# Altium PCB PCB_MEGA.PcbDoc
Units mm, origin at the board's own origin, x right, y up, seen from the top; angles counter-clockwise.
Board outline 45.21 x 64 mm, 2 copper layers (M1(Top_copper), M2(Bottom copper), stack 0.325 mm thick; 31 components, 22 nets, 132 pads, 19 vias.
Unrouted connection lines stored in the file: 13.
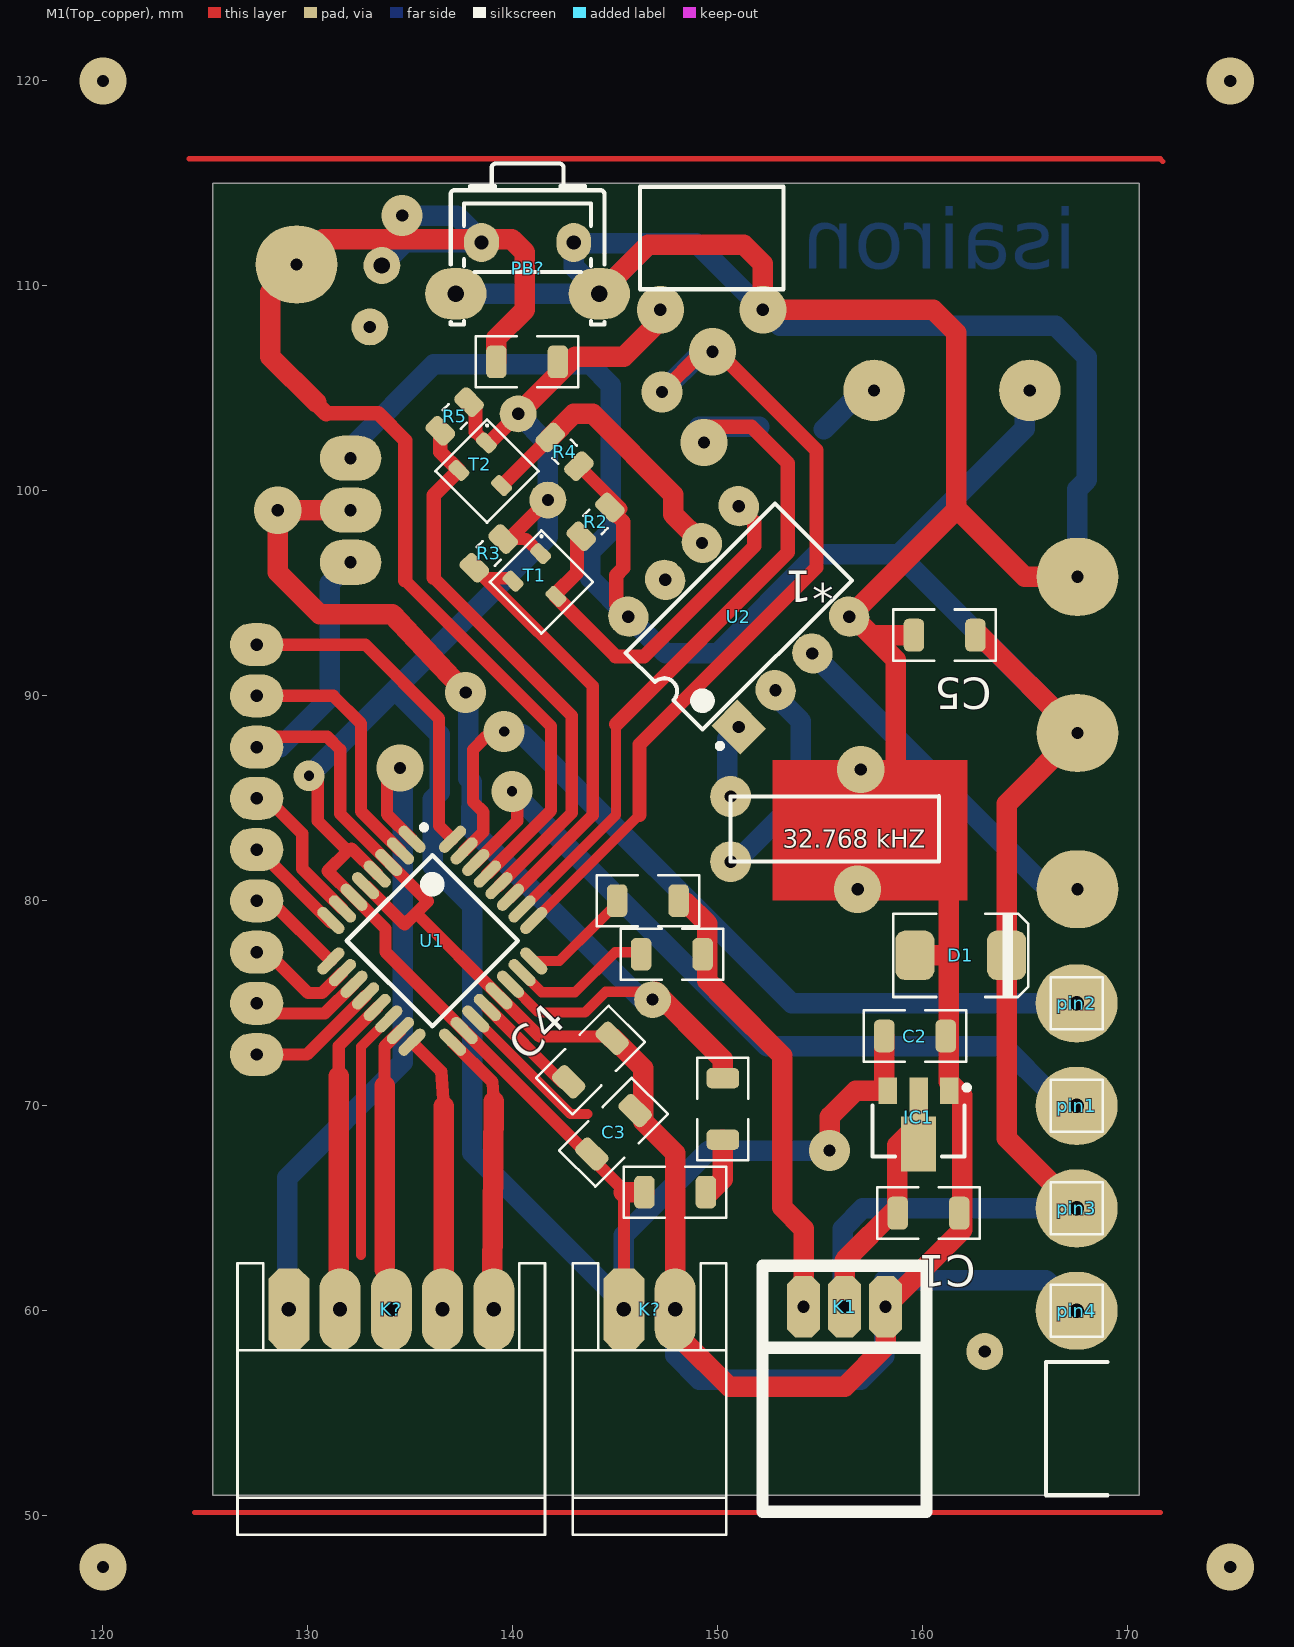
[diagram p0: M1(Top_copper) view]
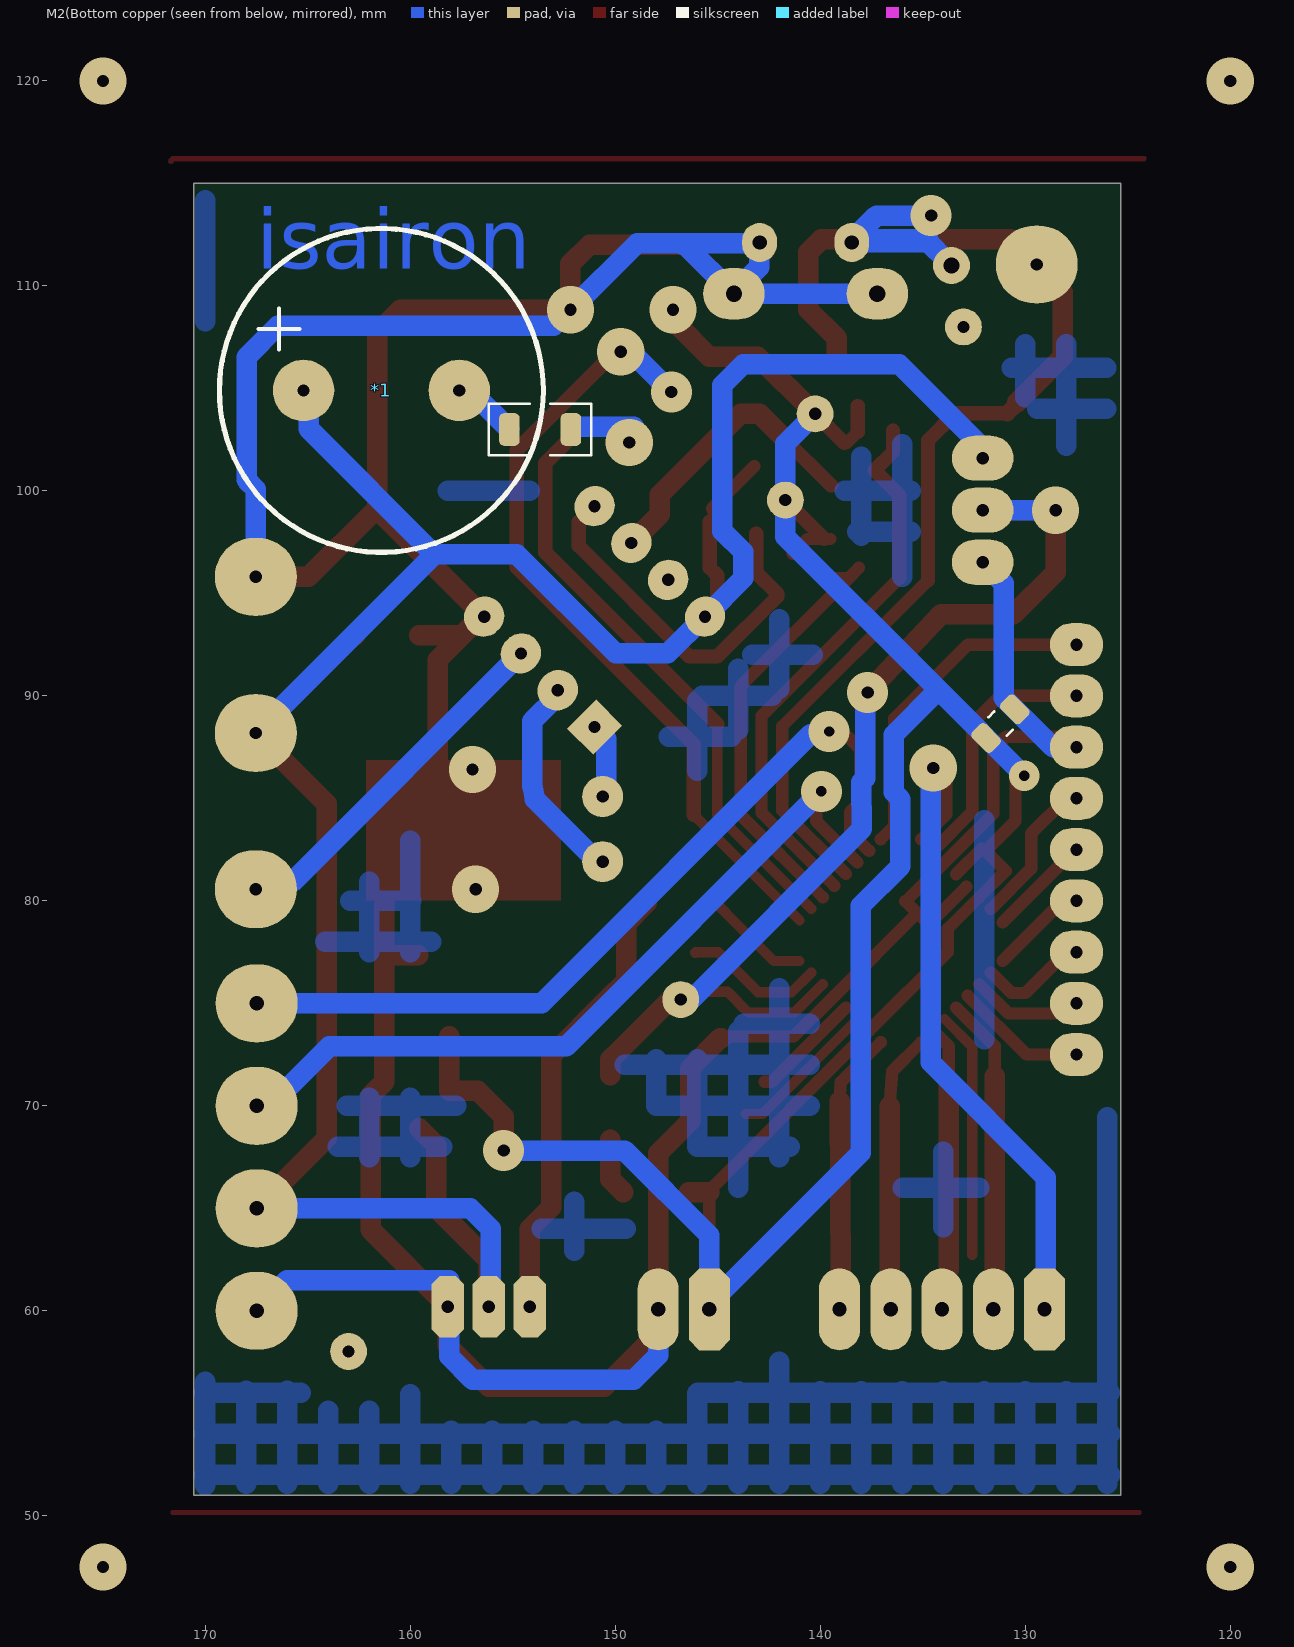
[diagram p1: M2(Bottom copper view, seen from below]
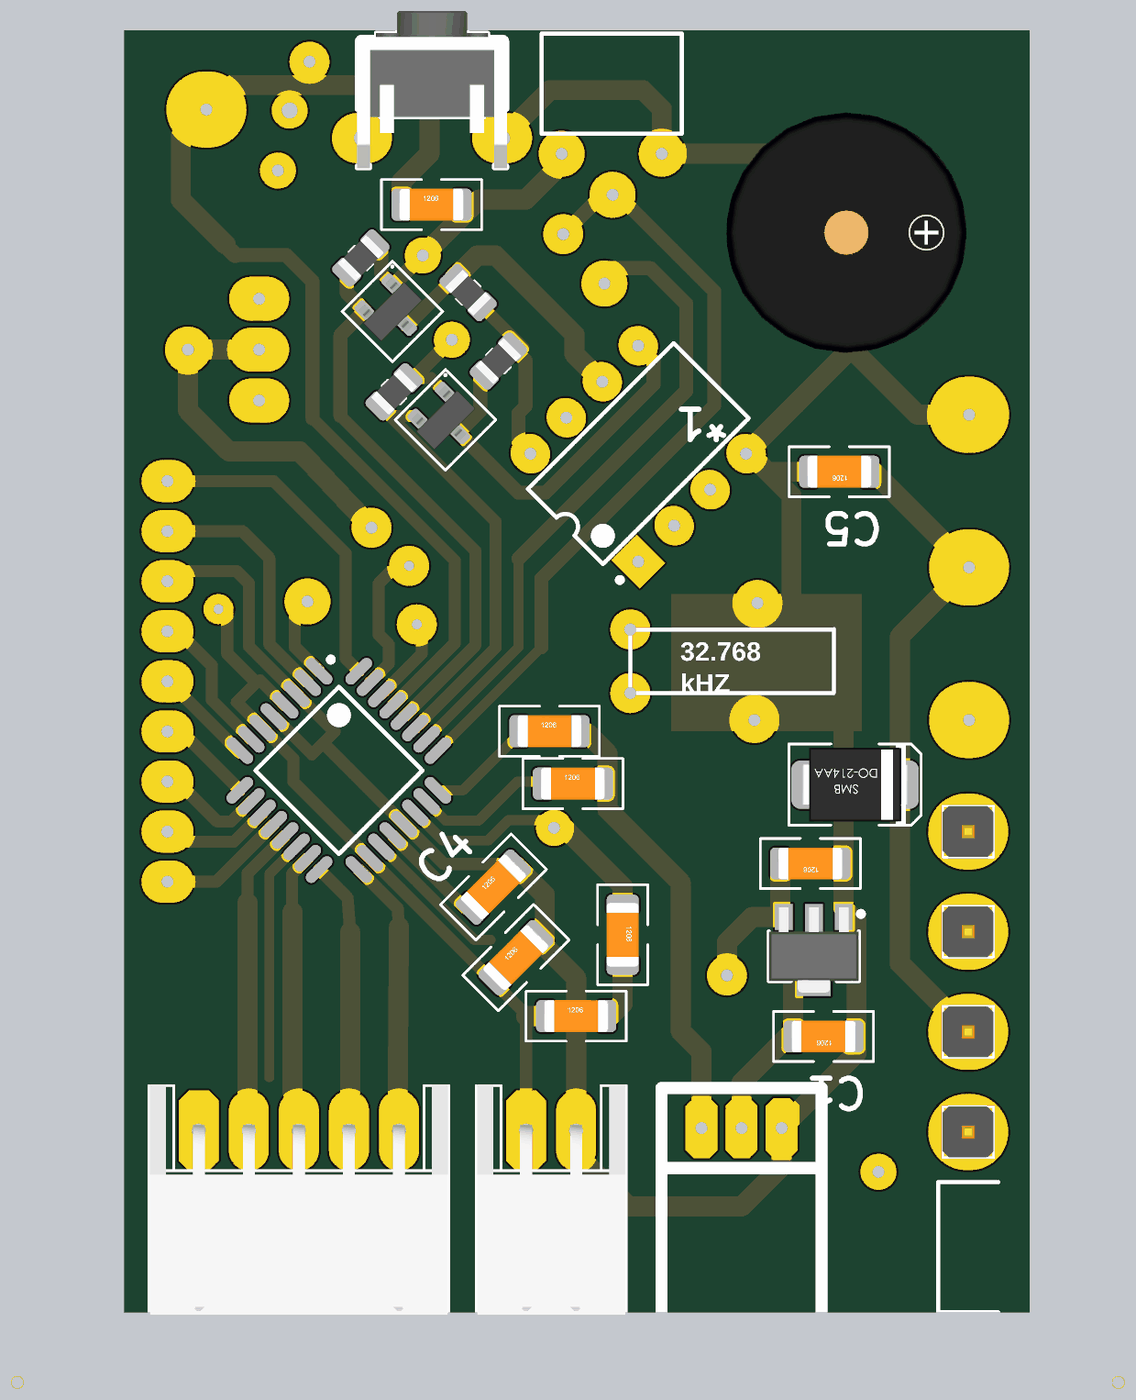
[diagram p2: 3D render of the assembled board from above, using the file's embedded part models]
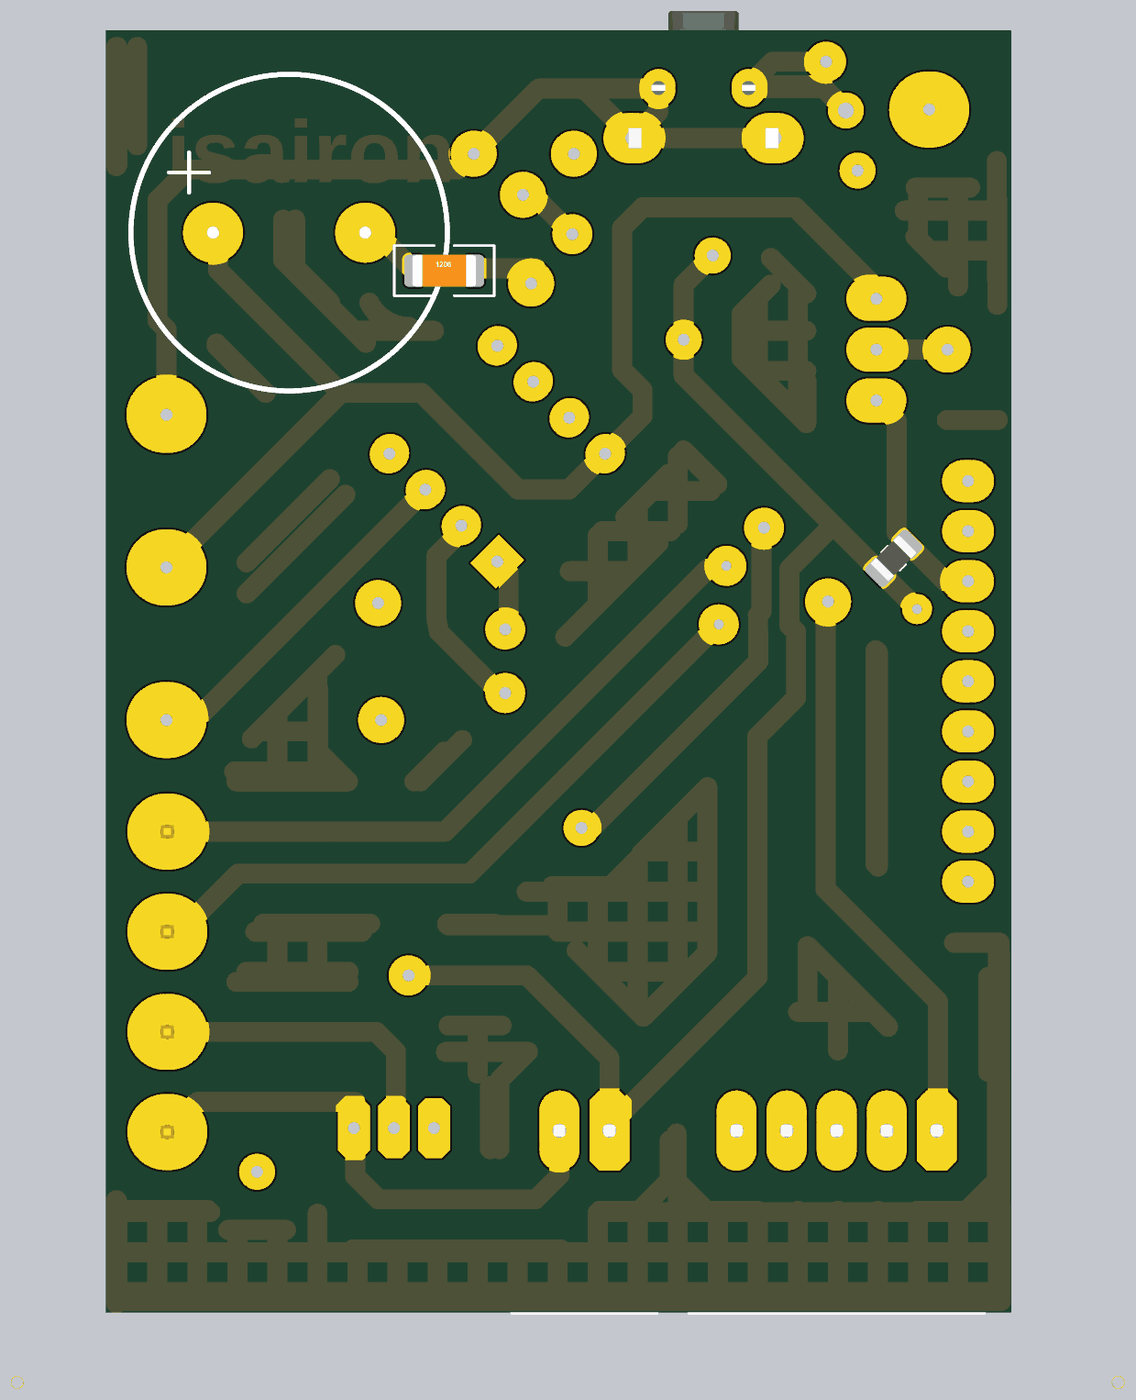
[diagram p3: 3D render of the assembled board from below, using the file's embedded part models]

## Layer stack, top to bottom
Top Solder: solder mask 0.0102, Solder Resist, Dk 3.5
M1(Top_copper): signal copper 0.0356
Dielectric 1: core 0.254, FR-4, Dk 4.2
M2(Bottom copper: signal copper 0.0356
Bottom Solder: solder mask 0.0102, Solder Resist, Dk 3.5

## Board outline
125.349,51 125.349,115 170.561,115 170.561,51

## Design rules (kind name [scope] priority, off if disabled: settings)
AssemblyTestPointUsage [All] p1 off:
AssemblyTestpoint [All] p1 off: testpointundercomponent=TRUE minsize=1.016 maxsize=2.54 preferedsize=1.524 minholesize=0 maxholesize=1.016 preferedholesize=0.813 testpointgrid=0.025 usegrid=TRUE gridtolerance=0 allowsidetop=TRUE allowsidebottom=TRUE
Clearance Clearance_GND [All vs InNet('No Net')] p1 off: gap=0.254 except(0.5: Arc-Poly Track-Poly SMDPad-Poly THPad-Poly Via-Poly Fill-Poly Poly-Poly; 0.7: Arc-Region Track-Region SMDPad-Region THPad-Region Via-Region Fill-Region Poly-Region Region-Region)
Clearance isairon_rule [All] p2 off: gap=0.254 // Для изучения
Clearance [All] p3: gap=0.254 except(1: Arc-Text Track-Text SMDPad-Text THPad-Text Via-Text Fill-Text Poly-Text Region-Text Text-Text; 1.5: Arc-Fill Arc-Poly Track-Fill Track-Poly SMDPad-Fill SMDPad-Poly THPad-Fill THPad-Poly Via-Fill Via-Poly Fill-Fill Fill-Poly Poly-Poly; 2: Arc-Region Track-Region SMDPad-Region THPad-Region Via-Region Fill-Region Poly-Region Region-Region)
ComponentClearance [All] p1: gap=0.5 collisioncheckmode=3 verticalgap=0.5 showdistances=FALSE
FabricationTestPointUsage [All] p1 off: valid=0 allowmultiple=FALSE
FabricationTestpoint [All] p1 off: side=3 testpointundercomponent=TRUE minsize=1.016 maxsize=2.54 preferedsize=1.524 minholesize=0 maxholesize=1.016 preferedholesize=0.813 testpointgrid=0.025 allowsidetop=TRUE allowsidebottom=TRUE usegrid=TRUE gridtolerance=0
PasteMaskExpansion [All] p1 off: expansion=0
PolygonConnect [All] p1: connectstyle=Relief reliefconductorwidth=0.254 reliefentries=4 polygonreliefangle="90 Angle" airgapwidth=0.254
RoutingVias [All] p1: holewidth=0.6 width=2 viastyle="Through Hole" minholewidth=0.5 minwidth=1.5 maxholewidth=1.5 maxwidth=2.2
SolderMaskExpansion [All] p1 off: expansion=0.102
Width [All] p1: maxlimit=1 minlimit=0.254 preferedwidth=0.5
24 further rules are at their usual default settings.

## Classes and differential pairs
component class SheetMEGA: *1 *2 C1 C2 C3 C4 C5 D1 IC1 K1 K? PB? pin1 pin2 pin3 pin4 R2 R3 R4 R5 T1 T2 U1 U2

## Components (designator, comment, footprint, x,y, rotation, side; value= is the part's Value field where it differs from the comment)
*1 "BUZZER HPM14AX" HPM14-AX 161.417,104.902 r180 bottom
C1 "100n" C1206(3216) 160.274,64.77 r180 top
C2 "100n" C1206(3216) 159.615,73.406 r180 top
C3 "100n" C1206(3216) 144.907,68.707 r45 top
C4 "100n" C1206(3216) 143.783,72.231 r45 top
C5 "100n" C1206(3216) 161.06,92.964 r180 top
D1 "SMBJ214-AA" "DO-214AA (SMB)" 161.849,77.343 r0 top
IC1 "Device" SOT89 159.79,68.774 r270 top
K1 "2mm 4-header" "SherKhan Con _3_PIN" 158.178,60.198 r180 top
K? "WS2R" WS2R 146.665,60.071 r180 top
K? "WS5R" WS5R 134.065,60.071 r180 top
PB? "Push Button" PB_ALPS_SKHHLMA010 140.716,110.871 r270 top
pin1 "H-1" J1 167.5,70 r0 top
pin2 "H-1" J1 167.5,75 r90 top
pin3 "H-1" J1 167.5,65 r90 top
pin4 "H-1" J1 167.5,60 r90 top
R2 "10k 0805" 0805 144.033,98.49 r225 top
R3 "10k 0805" 0805 138.821,96.951 r45 top
R4 "10k 0805" 0805 142.52,101.909 r135 top
R5 "10k 0805" 0805 137.16,103.632 r45 top
T1 "2N7002k" SOT23 141.389,95.559 r225 top
T2 "2N7002k" SOT23 138.738,100.968 r225 top
U1 "ATmega8A-AU" 32A_N 136.066,78.054 r315 top
U2 "DS1307" DIP8 151.017,93.866 r135 top
? "Comment" 0805 131.216,88.646 r135 bottom
? "Comment" C1206(3216) 147.752,77.394 r0 top
? "Comment" C1206(3216) 146.583,80.01 r0 top
? "Comment" C1206(3216) 150.241,69.85 r270 top
? "Comment" C1206(3216) 147.915,65.786 r0 top
? "Comment" C1206(3216) 153.67,102.997 r180 bottom
? "Comment" C1206(3216) 140.692,106.299 r0 top

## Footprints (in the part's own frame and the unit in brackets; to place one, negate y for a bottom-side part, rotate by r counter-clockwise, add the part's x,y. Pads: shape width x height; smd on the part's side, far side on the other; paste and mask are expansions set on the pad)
32A_N [mm] "Thin QFP, 32-Leads, Body 7x7mm, Pitch 0.8mm, IPC Medium Density"
  oval 1.65x0.55 smd: 1(-4.2,2.8) 2(-4.2,2) 3(-4.2,1.2) 4(-4.2,0.4) 5(-4.2,-0.4) 6(-4.2,-1.2) 7(-4.2,-2) 8(-4.2,-2.8) 17(4.2,-2.8) 18(4.2,-2) 19(4.2,-1.2) 20(4.2,-0.4) 21(4.2,0.4) 22(4.2,1.2) 23(4.2,2) 24(4.2,2.8)
  oval 0.55x1.65 smd: 9(-2.8,-4.2) 10(-2,-4.2) 11(-1.2,-4.2) 12(-0.4,-4.2) 13(0.4,-4.2) 14(1.2,-4.2) 15(2,-4.2) 16(2.8,-4.2) 25(2.8,4.2) 26(2,4.2) 27(1.2,4.2) 28(0.4,4.2) 29(-0.4,4.2) 30(-1.2,4.2) 31(-2,4.2) 32(-2.8,4.2)
  silkscreen extent -4.32,-2.95 2.95,3.75, body extent -3.5,-3.5 3.5,3.5, height 1.2
0805 [mil] "Metal Electrode Face (MELF) Resistor; Body 2 x 1.4 mm (LxDia)"
  rrect50% 38x54 smd: 1(-39,0) 2(39,0)
  silkscreen extent -8,-25 8,25, body extent -39,-25 39,25, height 19
C1206(3216) [mm]
  rrect50% 1x1.6 smd: 1(-1.5,0) 2(1.5,0)
  silkscreen extent -2.5,-1.25 2.5,1.25, body extent -1.6,-0.8 1.6,0.8, height 1
DIP8 [mm] "DIP, 8-Leads, Row Spacing 7.62mm, Pitch 2.54mm, Body 9.65x6.35mm"
  rect 2x1.8 hole 0.6: 1(-3.81,3.81)
  oval 2x1.9 hole 0.6: 2(-3.81,1.27) 3(-3.81,-1.27) 4(-3.81,-3.81) 5(3.81,-3.81) 6(3.81,-1.27) 7(3.81,1.27) 8(3.81,3.81)
  silkscreen extent -3.93,-5.15 2.65,5.23, body extent -3.6,-5.15 3.6,5.15, height 4.42
"DO-214AA (SMB)" [mil] "DO-214-AA/SMB; 2 C-Bend Leads; Body 5.3 x 3.6 mm, inc. leads (LxW)"
  rrect50% 75x95 smd: 1(-88,0) 2(88,0)
  silkscreen extent -130,-80 130,80, body extent -104,-73 104,73, height 87
HPM14-AX [mm]
  round 3 hole 0.6: 1(-3.8,0) 2(3.8,0)
  silkscreen extent -7.9,-7.9 7.9,7.9, body extent -6,-6 6,6, height 9.5
J1 [mm]
  round 3.5 hole 0.7: 1(0,0)
  silkscreen extent -1.27,-1.27 1.27,1.27, body extent -1.27,-1.27 1.27,1.27, height 10.1
PB_ALPS_SKHHLMA010 [mm] "Body 6x6mm, Stem height 3.85mm, Horizontal Pushbutton Switch, ALPS Serie SKHH"
  oval 1.9x1.7 hole 0.7: 1(-1.25,-2.25) 2(-1.25,2.25)
  oval 2.5x3 hole 0.8: 3(1.25,-3.5) 4(1.25,3.5)
  silkscreen extent -5.1,-3.75 2.75,3.75, body extent -5.1,-3.75 2.75,3.75, height 7.1
"SherKhan Con _3_PIN" [mm]
  oct 1.6x3 hole 0.6: 1(0,0) 2(2,0) 3(4,0)
  silkscreen extent -2,-2 6,10
SOT23 [mm] "SOT-23; 3 Leads; Body 3.0 x 2.6 mm Pitch 0.95mm"
  rrect50% 0.65x1 smd: 1(-0.95,-1) 2(0.95,-1) 3(0,1)
  silkscreen extent -1.78,-1.78 1.78,1.78, body extent -1.46,-1.23 1.46,1.24, height 1
SOT89 [mm] "SOT89-3, 3-Leads, Body 2.48x4.5mm"
  rect 1.3x0.9 smd: 1(-1.965,1.5) 3(-1.965,-1.5)
  rect 1.9x0.9 smd: 2(-1.665,0)
  rect 2.7x1.7 smd: 2(0.635,0)
  silkscreen extent -2.24,-2.25 1.24,2.48, body extent -2.44,-2.25 1.81,2.25, height 1.6
WS2R [mm]
  oct 2x4 hole 0.7: 1(1.25,0)
  oval 2x4 hole 0.7: 2(-1.25,0)
  silkscreen extent -3.75,-2.25 3.75,11, body extent -3.7,-2.3 3.7,9.2, height 6.1
WS5R [mm]
  oct 2x4 hole 0.7: 1(5,0)
  oval 2x4 hole 0.7: 2(2.5,0) 3(0,0) 4(-2.5,0) 5(-5,0)
  silkscreen extent -7.5,-2.25 7.5,11, body extent -7.45,-2.3 7.45,9.2, height 6.1

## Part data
C1 C2 C3 C4 C5: library part C_1206, "SMD-0805 50V Y5V +80/-20%"
D1: "Диод защитный двунаправленный. пробивается на 6.1"
IC1: library part MCP1703T-3302e/mb, "3.3VDO"
K1: library part "SherKhan con_3_PIN", "2mm_step"
K? K?: "2.5mm 3A/250V"
PB?: library part PB_ALPS_SKHHLMA010, "Push-Button Switch SPDT"
R2 R3 R4 R5: library part R-0805-1%, "SMD 0805 0.1W 1% 150V"
T1 T2: "N-MOS 60V 7.5om 0.115mA"
U1: "8-bit AVR Microcontroller, 8KB Flash, 512 Bytes EEPROM, 1KB SRAM, 32-pin TQFP, Industrial Grade (-40°C to 85°C)"
U2: "64 X 8 Serial Real-Time Clock"

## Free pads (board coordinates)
  round 2 hole 0.6 unplated: 0(150.622,85.09) 1(150.622,81.915)
  oval 2.6x2.1 hole 0.6 unplated: 23(127.5,72.5) 24(127.5,75) 25(127.5,77.5) 26(127.5,80) 27(127.5,82.5) 28(127.5,85) 29(127.5,87.5) 30(127.5,90) 30(127.5,92.5)
  oval 4x3.8 hole 0.6 unplated: 31(167.544,95.808) 32(167.5,60) 32(167.544,88.188) 34(129.444,111.048)
  oval 4x3.8 hole 0.6: 33(167.5,65) 33(167.544,80.568) 34(167.5,70) 35(167.5,75)
  round 1.8 hole 0.6 unplated: 38(140.256,103.759) 39(141.707,99.554) 40(163.017,58.014) 41(133.02,108.001) 42(146.812,75.184)
  oval 3x2.2 hole 0.6 unplated: 43(132.08,96.52) 44(132.08,99.06) 47(132.08,101.6)
  round 1.8 hole 0.8 unplated: 48(133.604,110.998)

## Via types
v1: diameter 2.3, hole 0.6, M1(Top_copper) to M2(Bottom copper, 12 vias
v2: diameter 2, hole 0.6, M1(Top_copper) to M2(Bottom copper, 4 vias
v3: diameter 2, hole 0.5, M1(Top_copper) to M2(Bottom copper, 2 vias
v4: diameter 1.5, hole 0.5, M1(Top_copper) to M2(Bottom copper, 1 vias

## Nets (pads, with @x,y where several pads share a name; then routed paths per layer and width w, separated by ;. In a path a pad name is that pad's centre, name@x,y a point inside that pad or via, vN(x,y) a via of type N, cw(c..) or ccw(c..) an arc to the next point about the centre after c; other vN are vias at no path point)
3.3V: C3.1 IC1.3 K?.1@145.415,60.071 pad.38 pad.39 R3.2 R5.2 T1.1 T2.1 U1.4 U1.6 U1.18 | length 127.2
  M1(Top_copper) w0.6: v4(130.048,86.106) 130.302,86.106 130.48,85.928 130.48,83.896 131.938,82.438 130.961,81.461 U1.6 133.787,78.636 133.787,77.504 U1.18 145.415,65.876 K?.1@145.415,60.071 ; 132.129,82.552 U1.4@133.379,81.302 ; 138.176,102.873 T2.1 T2.1@138.844,102.347 ; R3.2@139.805,97.651 R3.2 140.64,97.651 T1.1
  M1(Top_copper) w0.7: 138.176,102.873 R5.2@138.176,104.14 ; T2.1@138.844,102.347 pad.38 ; R3.2@139.805,97.651 pad.39
  M1(Top_copper) w1: pad.38 143.05,106.553 145.415,106.553 147.066,108.204 147.066,109.093
  M2(Bottom copper w1: v4(130.048,86.106) 134.239,90.297 ; pad.38 141.707,102.307 pad.39 141.707,97.765 134.239,90.297 ; K?.1@145.415,60.071 K?.1@145.415,60.325 ; v2(155.448,67.818) 149.555,67.818 145.415,63.678 K?.1@145.415,60.325 ; 134.239,90.297 136.423,88.113 136.423,85.293 136.093,84.963 136.093,81.686 138.024,79.756 138.024,67.716 K?.1@145.415,60.325
5.0V: *1.1 C1.2 C5.1 D1.2 IC1.2@159.79,70.439 K1.2 pad.32@167.544,88.188 pad.33@167.5,65 pad.47 pin3.1 R2.1 R4.1 U2.8 | length 129.3
  M1(Top_copper) w0.6: R4.1 R2.1@145.292,99.137 ; U2.8@145.034,94.462 U2.8
  M1(Top_copper) w0.7: R2.1@144.755,99.136 145.39,98.501 145.39,96.241 145.034,95.885 U2.8@145.034,94.462
  M1(Top_copper) w1: K1.2 156.178,62.452 158.75,65.024 158.75,68.072 159.576,68.897 ; C5.1@162.768,92.964 167.544,88.188 164.084,84.728 164.084,68.416 pin3.1
  M2(Bottom copper w1: pad.47@132.08,102.108 136.144,106.172 143.764,106.172 144.78,105.156 144.78,98.044 143.764,97.028 143.764,95.732 U2.8 ; U2.8@145.656,93.866 147.447,92.075 149.987,92.075 154.813,96.901 158.831,96.901 ; 156.083,64.008 157.075,65 pin3.1 ; *1.1@164.973,104.511 164.973,103.043 158.831,96.901 ; pad.32@167.544,88.188 158.831,96.901
AREF: C4.1 U1.20 | length 5.5
  M1(Top_copper) w0.6: U1.20 142.383,71.171 C4.1
GND: C3.2 C4.2 C5.2 IC1.1 K?.2@147.915,60.071 PB?.2 PB?.4 pin4.1 U1.3 U1.5 U1.21 U2.4 | length 141.2
  M1(Top_copper) w0.6: 128.143,88.011 130.937,88.011 131.572,87.376 131.572,84.244 U1.3 135.834,79.983 135.852,79.983 135.268,79.399 ; U1.5@132.876,80.687 134.716,78.847 135.268,79.399 ; C4.2@144.704,73.152 144.475,73.381 141.305,73.381 U1.21 135.286,79.399 135.268,79.399
  M1(Top_copper) w1: PB?.4 146.609,112.014 151.257,112.014 152.193,111.078 152.193,108.839 160.503,108.839 161.62,107.721 161.62,99.081 U2.4 ; C4.2 144.894,73.292 146.355,71.831 146.355,69.24 147.915,67.68 K?.2@147.915,60.071 ; 157.5,92.944 157.52,92.964 C5.2 ; 158.178,60.198 161.925,63.945 161.925,70.521 161.266,71.18 161.266,80.621 161.29,80.645
  M2(Bottom copper w1: 137.084,109.55 137.155,109.621 PB?.4 146.634,112.039 146.761,112.039 ; K?.2@147.915,60.071 147.915,57.825 149.098,56.642 156.972,56.642 158.115,57.785 158.115,61.496 158.111,61.5 166,61.5
INT0: K?.1@129.065,60.071 U1.32 | length 43.4
  M1(Top_copper) w0.6: 127.5,92.5 132.798,92.5 136.398,88.9 136.398,83.661 U1.32
  M2(Bottom copper w1: K?.1@129,62 129,66.5 134.62,72.12 v1@134.62,86.5
  other v1: 134.493,86.487
MOSI: K?.3 U1.15 | length 13.8
  M1(Top_copper) w0.6: 133.731,70.231 133.731,72.891 ; 133.731,72.891 U1.15 133.731,72.891
  M1(Top_copper) w1: K?.3@133.746,62 133.746,70.978
NetC1_1: C1.1 D1.1 IC1.2@159.79,68.139 K1.1 | length 26
  M1(Top_copper) w1: 148.234,58.598 150.546,56.286 156.185,56.286 158.178,58.28 K1.1 ; 156.718,93.726 158.674,91.77 158.674,85.979 ; D1.1 161.266,77.343
  M2(Bottom copper w1: 166,61.5 167.5,60
  other v1: 156.82,80.569 156.972,86.411
NetK?_4: K?.4 U1.16 | length 11.7
  M1(Top_copper) w0.6: U1.16 136.5,71.68 136.627,69.977
  M1(Top_copper) w1: K?.4@136.627,62 136.627,69.977
NetR2_2: R2.2 T1.3 U2.5 | length 18.9
  M1(Top_copper) w0.6: T1.3 T1.3@142.096,94.979 ; U2.5 151.781,98.491
  M1(Top_copper) w0.7: T1.3 145.025,91.923 146.393,91.923 151.781,97.312 151.781,98.491 ; T1.3@142.096,94.979 143.129,96.012 R2.2@143.129,97.917
NetR4_2: R4.2 T2.3 U2.6 | length 14.6
  M1(Top_copper) w0.6: T2.3 T2.3@139.471,100.261 ; U2.6@148.981,97.459 U2.6
  M1(Top_copper) w0.7: T2.3@139.471,100.261 R4.2
  M1(Top_copper) w1: R4.2 142.969,103.759 143.891,103.759 147.828,99.822 147.828,98.852 U2.6
NetU1_7: U1.7 | length 6.9
  M1(Top_copper) w0.6: 128,85 129.718,83.282 129.718,81.573 U1.7
NetU1_8: U1.8 | length 5
  M1(Top_copper) w0.6: 127.58,82.478 U1.8@131.116,78.942
NetU1_9: U1.9 | length 4.3
  M1(Top_copper) w0.6: 128,80 128.18,80 U1.9
NetU1_10: U1.10 | length 5.4
  M1(Top_copper) w0.6: 127.5,77.5 128,77.5 130,75.5 130.684,75.5 U1.10
NetU1_11: U1.11 | length 5
  M1(Top_copper) w0.6: 128,75 128.5,74.5 130.815,74.5 U1.11
NetU1_12: U1.12 | length 6.5
  M1(Top_copper) w0.6: 127.5,72.5 129.946,72.5 U1.12
RESET: PB?.3 U1.29 | length 30.6
  M1(Top_copper) w0.6: 134.747,95.631 141.859,88.519 141.859,84.413 U1.29
  M1(Top_copper) w0.7: 130.886,103.784 133.426,103.784 134.747,102.464 134.747,95.631
  M1(Top_copper) w0.8: 130.353,104.318 130.886,103.784
RX: pad.34@167.5,70 pin1.1 U1.30 | length 36.4
  M1(Top_copper) w0.6: U1.30 140.208,83.893 v3@140.208,85.09
  M2(Bottom copper w1: v3(139.954,85.344) 152.4,72.898 163.957,72.898 pin1.1@166.243,70.612
SCK: K?.5 U1.17 | length 12.3
  M1(Top_copper) w0.6: U1.17 139,71.16 139.065,70.231
  M1(Top_copper) w1: K?.5@139,61.619 139.065,70.231
SCL: R5.1 T2.2 U1.28 | length 27.3
  M1(Top_copper) w0.6: 136.144,95.758 142.875,89.027 142.875,84.297 U1.28
  M1(Top_copper) w0.7: 136.144,95.758 136.144,99.789 T2.2 136.46,101.903 R5.1
SDA: R3.1 T1.2 U1.27 | length 21.4
  M1(Top_copper) w0.6: R3.1 138.636,95.736 ; T1.2@139.869,95.736 138.636,95.736 ; U1.27 143.891,84.182 143.891,90.48 138.636,95.736
TX: U1.31 | length 40.6
  M1(Top_copper) w0.6: U1.31 138.557,83.373 138.557,84.328 138.049,84.836 138.049,87.376 v3@138.684,88.011
  M2(Bottom copper w1: v3(139.573,88.265) 139.573,88.773 140.208,88.138 140.462,88.138 153.6,75 167.5,75
pads on no net: *1.2 ?.1 ?.2 C2.1 C2.2 K1.3 K?.2@131.565,60.071 PB?.1 pin2.1 U1.1 U1.2 U1.13 U1.14 U1.19 U1.22 U1.23 U1.24 U1.25 U1.26 U2.1 U2.2 U2.3 U2.7
copper on no net: | length 458.2
  M1(Top_copper) w0.254: 124.206,116.205 171.577,116.205 171.704,116.078 ; 124.46,50.165 171.577,50.165
  M1(Top_copper) w0.5: 132.588,62.738 132.588,72.879 133.944,74.235 ; 138.187,74.235 142.826,69.596 143.637,69.596 ; 139.884,75.932 141.267,74.549 143.002,74.549 143.51,74.549 144.526,75.565 146.939,75.565 ; 140.45,76.498 141.408,75.54 143.027,75.54 144.983,77.495 146.075,77.495 146.101,77.47 ; 140.45,79.609 145.034,84.194 145.034,88.621 ; 141.015,77.064 142.266,77.064 144.094,78.892 144.983,79.781 144.983,80.137 ; 141.015,79.044 146.177,84.205 ; v1@149.233,106.79 v1(149.736,106.79)
  M1(Top_copper) w0.6: 128,92.5 128.171,92.329 ; 128.5,90 131.234,90 132.588,88.646 132.588,84.36 134.51,82.438 ; 131.5,71.446 131.5,72.922 133.379,74.801 ; 133.858,86.233 133.858,84.221 135.076,83.003
  M1(Top_copper) w0.7: 145.034,88.621 153.416,97.003 153.416,101.346 151.638,103.124 v1@149.225,103.124 ; 146.177,84.205 146.177,87.63 154.813,96.266 154.813,101.981 v1@149.86,106.934 ; v2(147.269,104.826) v1@149.233,106.79
  M1(Top_copper) w1: 130.404,104.318 128.168,106.553 128.168,109.703 129.261,110.795 130.734,112.268 134.747,112.268 139.954,112.268 140.589,111.633 140.589,108.839 139.192,107.442 139.192,106.299 ; 131.5,62 131.5,71.446 ; 132.08,99.06 v1(128.524,99.06) 128.524,96.037 130.581,93.98 134.112,93.98 v2(137.693,90.17) ; 145.415,65.786 146.415,65.786 ; 146.939,75.565 149.86,72.644 150.241,72.263 150.241,71.501 ; v1@147.447,109.22 v1@147.574,109.22 ; 148.463,79.908 149.479,78.892 149.479,77.495 149.479,76.098 150.368,75.209 153.137,72.441 153.137,65.049 154.178,64.008 154.178,60.198 ; 149.606,65.786 150.241,66.421 150.241,68.35 ; 155.448,67.818 155.448,69.469 155.575,69.596 156.718,70.739 158.115,70.739 158.115,73.406 ; 161.696,99.085 164.974,95.808 167.544,95.808 ; 162.687,92.964 162.768,92.964
  M2(Bottom copper w1: 127.5,87.5 128.648,87.5 131.064,89.916 131.064,95.504 132.08,96.52 ; v1(128.524,99.06) 132.08,99.06 ; 132.08,101.6 132.08,102.108 ; 133.858,111.252 134.727,112.121 138.466,112.121 ; v2(134.595,113.436) 137.262,113.436 138.43,112.268 ; 134.747,112.268 138.557,112.268 ; v2(137.693,90.17) 137.82,90.043 137.82,85.976 137.998,85.795 137.972,83.516 146.304,75.184 146.812,75.184 ; 144.323,109.576 142.977,110.922 142.977,112.09 148.942,112.09 v1(152.193,108.839) ; 145.629,93.866 145.656,93.866 ; v2(147.269,104.826) 149.174,106.731 v1@149.708,106.731 ; v1@149.098,103.124 152.019,103.124 ; 150.454,85.43 150.454,87.915 151.017,88.478 ; 150.876,81.915 153.924,84.963 154.051,85.598 154.051,88.773 152.813,90.011 152.813,90.274 ; v1@152.095,108.966 153.01,108.052 166.472,108.052 167.996,106.528 167.996,100.533 167.544,100.082 167.544,95.808 ; 154.609,92.07 165.781,80.899 167.894,80.899 ; 155.17,102.997 157.075,104.902 157.617,104.902 ; 156.083,64.008 156.083,61.528 156.111,61.5 ; 166.243,70.104 166.243,70.612
  other v1: 120,47.5 175,47.5 149.327,102.362 147.193,108.839 120,120 175,120

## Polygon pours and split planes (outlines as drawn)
no net on M2(Bottom copper "AutoNaming" (hatched 90Degree grid 2 track 1, remove dead copper, pour order 0): 126.086,114.275 126.187,114.173 170.053,114.173 170.053,51.435 169.926,51.562 125.857,51.562

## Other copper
M1(Top_copper):
  rectangle net NetC1_1: 152.654,80.01 162.179,86.868
M2(Bottom copper:
  text "isairon" at 167.513,109.88 h5

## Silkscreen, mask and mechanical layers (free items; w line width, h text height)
Top Overlay:
  lines w0.2: 160.782,81.915 150.622,81.915 150.622,85.09 160.782,85.09 ; 160.791,81.931 160.791,85.106 ; 169,51 166,51 166,57.5 169,57.5 ; 146.193,109.839 146.193,114.839 153.193,114.839 153.193,109.839 146.193,109.839
  text "32.768 kHZ" at 153.162,82.296 h1.5
0 (Board_boarders):
  circle w0.254: c163,58 r1.5
  circle w0.254: c133,108 r1.5
  lines w0.5: 120.396,120.015 125.349,115.062 125.349,115 ; 121.158,46.863 125.295,51 125.349,51 ; 170.561,51.181 174.498,47.244 ; 170.561,114.808 170.561,114.935 175.387,119.761 ; 125.349,51 170.561,51 170.561,115 125.349,115 ; 125.349,51 125.349,115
